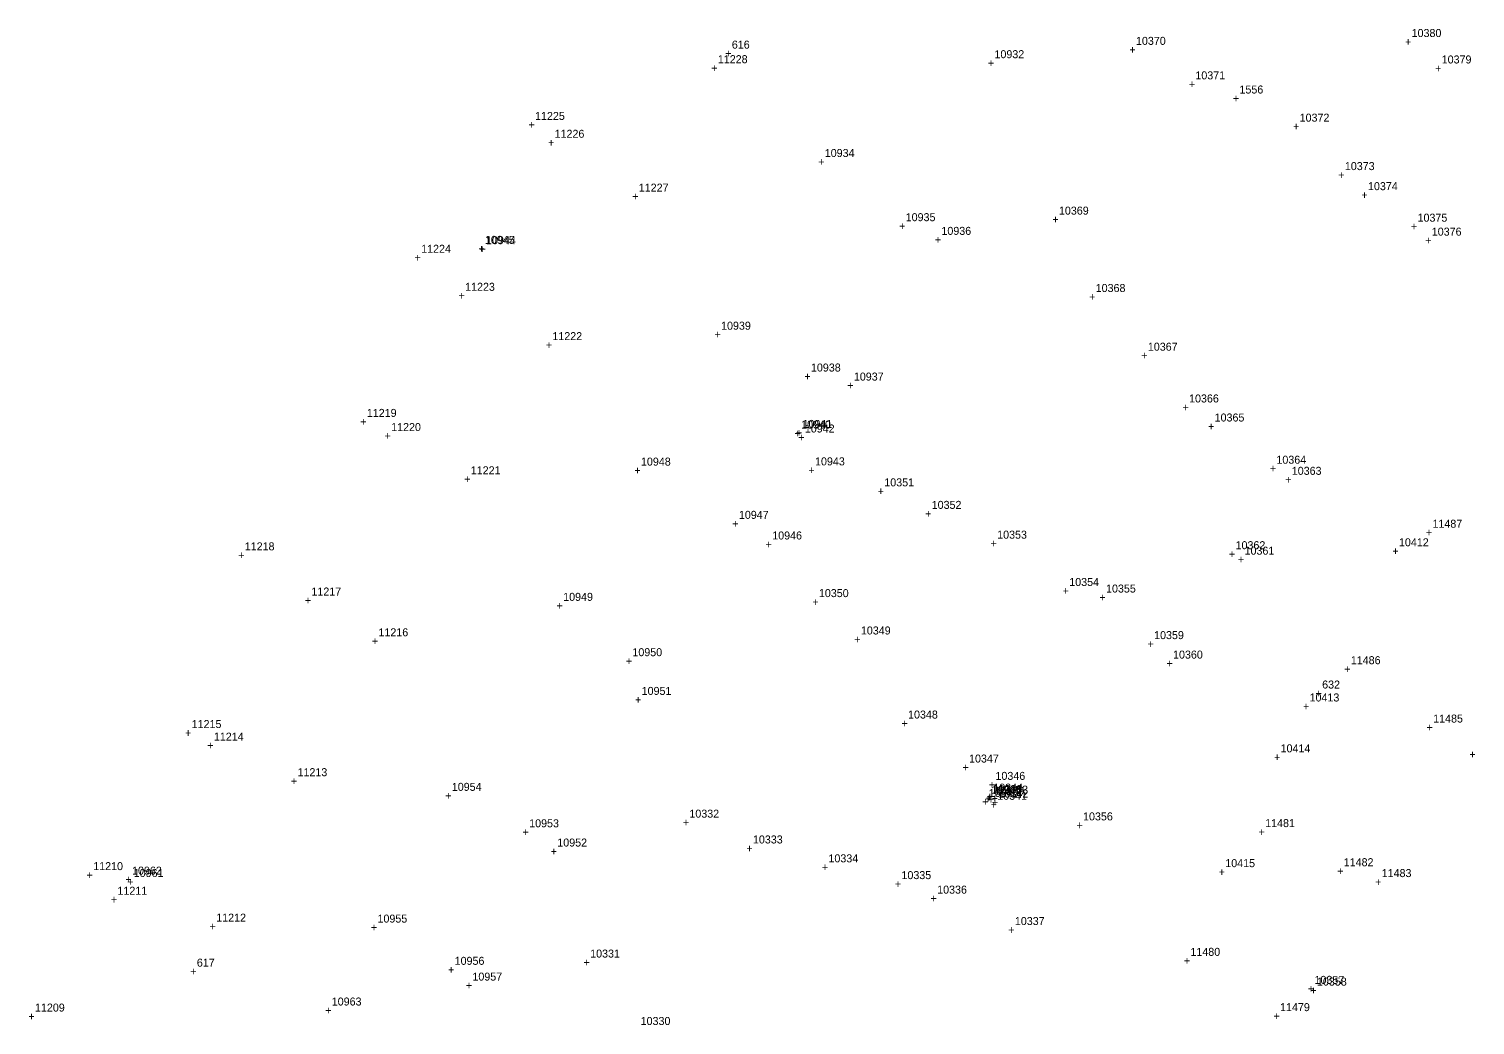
# Model space of a CAD drawing. Extents: x 1160051 to 1162814, y 614604 to 619560.
# Drawn here: x 1160823.2 to 1161275, y 616775.5 to 617086.8 of the extents above; entities that cross this region are included whole.
import ezdxf

# ---------------------------------------------------------------- set-up
doc = ezdxf.new("R2010")
doc.units = 0
for name, color, linetype in [('S_Control_Temp_Traverse', 7, 'Continuous'), ('S_Drainage_Culvert_Top', 7, 'Continuous'), ('S_Drainage_Invert', 7, 'Continuous'), ('S_Ground_Elevation', 7, 'Continuous'), ('S_Guardrail_Beam', 7, 'Continuous'), ('S_Utilities_UG_BoringLocation', 7, 'Continuous')]:
    doc.layers.add(name, color=color, linetype=linetype)

msp = doc.modelspace()

# ---------------------------------------------------------------- texts
at = {"layer": 'S_Control_Temp_Traverse'}
for s, p in [('616', (1161042.8, 617080.64)), ('+', (1161040.74, 617077.89)), ('632', (1161227.2, 616880.64)), ('+', (1161225.14, 616877.89)), ('617', (1160875.69, 616793.72)), ('+', (1160873.63, 616790.97))]:
    msp.add_text(s, height=2.5, dxfattribs=at).set_placement(p)
at = {"layer": 'S_Drainage_Culvert_Top'}
for s, p in [('10944', (1160966.03, 617019.51)), ('+', (1160963.97, 617016.76)), ('10941', (1161064.89, 616962.09)), ('+', (1161062.83, 616959.34)), ('10339', (1161124.84, 616847.45)), ('+', (1161122.78, 616844.7)), ('10961', (1160855.97, 616821.74)), ('+', (1160853.91, 616818.99)), ('+', (1161222.75, 616785.59)), ('10357', (1161224.81, 616788.34))]:
    msp.add_text(s, height=2.5, dxfattribs=at).set_placement(p)
at = {"layer": 'S_Drainage_Invert'}
for s, p in [('10945', (1160965.69, 617019.63)), ('+', (1160963.63, 617016.88)), ('10940', (1161064.45, 616961.89)), ('+', (1161062.39, 616959.14)), ('10338', (1161124.22, 616847.95)), ('+', (1161122.16, 616845.2)), ('10962', (1160855.45, 616822.48)), ('+', (1160853.38, 616819.73)), ('+', (1161223.53, 616785.05)), ('10358', (1161225.59, 616787.8))]:
    msp.add_text(s, height=2.5, dxfattribs=at).set_placement(p)
at = {"layer": 'S_Ground_Elevation'}
for s, p in [('10380', (1161255.15, 617084.27)), ('10932', (1161124.84, 617077.65)), ('+', (1161166.98, 617079.07)), ('10370', (1161169.04, 617081.82)), ('+', (1161253.09, 617081.52)), ('11228', (1161038.43, 617076.09)), ('+', (1161122.78, 617074.9)), ('10379', (1161264.54, 617076.01)), ('+', (1161036.36, 617073.34)), ('10371', (1161187.6, 617071.04)), ('+', (1161262.48, 617073.26)), ('+', (1161185.54, 617068.29)), ('+', (1160979.27, 617055.6)), ('11225', (1160981.33, 617058.35)), ('10372', (1161220.17, 617057.82)), ('11226', (1160987.44, 617052.78)), ('+', (1161218.11, 617055.07)), ('+', (1160985.38, 617050.03)), ('10934', (1161071.83, 617046.77)), ('+', (1161069.77, 617044.02)), ('10373', (1161234.29, 617042.68)), ('+', (1161232.23, 617039.93)), ('+', (1161011.67, 617033.2)), ('11227', (1161013.73, 617035.95)), ('+', (1161239.46, 617033.66)), ('10374', (1161241.52, 617036.41)), ('10369', (1161144.98, 617028.76)), ('+', (1161095.05, 617023.96)), ('10935', (1161097.11, 617026.71)), ('+', (1161142.92, 617026.01)), ('+', (1161254.94, 617023.8)), ('10375', (1161257, 617026.55)), ('+', (1161106.2, 617019.68)), ('10936', (1161108.27, 617022.43)), ('11224', (1160945.76, 617016.83)), ('+', (1160943.7, 617014.08)), ('+', (1160957.43, 617002.2)), ('11223', (1160959.49, 617004.95)), ('+', (1161154.4, 617001.83)), ('10368', (1161156.46, 617004.58)), ('10939', (1161039.44, 616992.79)), ('11222', (1160986.75, 616989.53)), ('+', (1161037.38, 616990.04)), ('+', (1160984.69, 616986.78)), ('+', (1161170.69, 616983.48)), ('10367', (1161172.75, 616986.23)), ('10938', (1161067.51, 616979.72)), ('+', (1161065.45, 616976.97)), ('+', (1161078.86, 616974.14)), ('10937', (1161080.92, 616976.89)), ('10366', (1161185.63, 616970.05)), ('11219', (1160928.79, 616965.54)), ('+', (1161183.57, 616967.3)), ('+', (1160926.73, 616962.79)), ('11220', (1160936.39, 616961.12)), ('10942', (1161065.61, 616960.66)), ('+', (1161191.55, 616961.35)), ('10365', (1161193.61, 616964.1)), ('+', (1160934.33, 616958.37)), ('+', (1161063.55, 616957.91)), ('11221', (1160961.25, 616947.6)), ('+', (1161012.36, 616947.57)), ('10948', (1161014.42, 616950.32)), ('+', (1161066.73, 616947.64)), ('10943', (1161068.79, 616950.39)), ('+', (1161210.85, 616948.16)), ('10364', (1161212.91, 616950.91)), ('+', (1160959.19, 616944.85)), ('10351', (1161090.43, 616943.83)), ('+', (1161088.37, 616941.08)), ('10947', (1161045.01, 616933.68)), ('+', (1161103.17, 616934.04)), ('10352', (1161105.23, 616936.79)), ('+', (1161042.95, 616930.93)), ('11487', (1161261.66, 616930.91)), ('+', (1161053.36, 616924.48)), ('10946', (1161055.42, 616927.23)), ('+', (1161123.62, 616924.73)), ('10353', (1161125.68, 616927.48)), ('10362', (1161200.15, 616924.19)), ('+', (1161259.6, 616928.16)), ('+', (1160888.59, 616921.08)), ('11218', (1160890.65, 616923.83)), ('+', (1161198.08, 616921.44)), ('10354', (1161148.2, 616912.69)), ('10355', (1161159.69, 616910.64)), ('+', (1160909.42, 616906.96)), ('11217', (1160911.48, 616909.71)), ('10949', (1160990.12, 616908.05)), ('+', (1161067.94, 616906.47)), ('10350', (1161070, 616909.22)), ('+', (1161146.14, 616909.94)), ('+', (1161157.63, 616907.89)), ('+', (1160988.06, 616905.3)), ('11216', (1160932.42, 616896.97)), ('10349', (1161083.11, 616897.54)), ('+', (1160930.36, 616894.22)), ('+', (1161081.05, 616894.79)), ('+', (1161172.65, 616893.34)), ('10359', (1161174.71, 616896.09)), ('10950', (1161011.74, 616890.75)), ('11486', (1161236.15, 616888.25)), ('+', (1161009.68, 616888)), ('+', (1161234.09, 616885.5)), ('+', (1161012.57, 616875.9)), ('10951', (1161014.63, 616878.65)), ('10348', (1161097.85, 616871.26)), ('11485', (1161261.88, 616870.01)), ('11215', (1160874.07, 616868.29)), ('+', (1161095.79, 616868.51)), ('+', (1161259.82, 616867.26)), ('+', (1160872.01, 616865.54)), ('+', (1160878.95, 616861.61)), ('11214', (1160881.01, 616864.36)), ('10347', (1161116.9, 616857.51)), ('+', (1161273.18, 616858.83)), ('11213', (1160907.14, 616853.25)), ('+', (1161114.84, 616854.76)), ('10346', (1161125.15, 616852.09)), ('+', (1160905.08, 616850.5)), ('10954', (1160955.33, 616848.67)), ('+', (1161123.09, 616849.34)), ('10345', (1161123.87, 616847.66)), ('10344', (1161124.47, 616848.43)), ('10343', (1161126.03, 616847.8)), ('+', (1160953.27, 616845.92)), ('+', (1161121.01, 616844.01)), ('+', (1161121.81, 616844.91)), ('+', (1161122.41, 616845.68)), ('10340', (1161123.07, 616846.76)), ('+', (1161123.65, 616843.12)), ('+', (1161123.97, 616845.05)), ('+', (1161124.06, 616843.79)), ('10341', (1161125.71, 616845.87)), ('10342', (1161126.12, 616846.54)), ('10332', (1161029.54, 616840.29)), ('10356', (1161152.51, 616839.43)), ('+', (1160977.44, 616834.53)), ('10953', (1160979.5, 616837.28)), ('+', (1161027.48, 616837.54)), ('+', (1161150.45, 616836.68)), ('+', (1161207.34, 616834.58)), ('11481', (1161209.4, 616837.33)), ('10952', (1160988.28, 616831.26)), ('10333', (1161049.39, 616832.22)), ('+', (1160986.22, 616828.51)), ('+', (1161047.33, 616829.47)), ('10334', (1161072.98, 616826.32)), ('11482', (1161233.94, 616825.11)), ('+', (1160841.25, 616821.13)), ('11210', (1160843.32, 616823.88)), ('+', (1161070.91, 616823.57)), ('10335', (1161095.79, 616821.08)), ('+', (1161231.88, 616822.36)), ('11483', (1161245.8, 616821.71)), ('11211', (1160850.89, 616816.2)), ('+', (1161093.73, 616818.33)), ('10336', (1161106.94, 616816.54)), ('+', (1161243.74, 616818.96)), ('+', (1160848.83, 616813.45)), ('+', (1161104.88, 616813.79)), ('11212', (1160881.74, 616807.78)), ('10955', (1160932.12, 616807.49)), ('10337', (1161131.21, 616806.72)), ('+', (1160879.68, 616805.03)), ('+', (1160930.06, 616804.74)), ('+', (1161129.15, 616803.97)), ('10956', (1160956.22, 616794.29)), ('+', (1160996.49, 616793.81)), ('10331', (1160998.55, 616796.56)), ('+', (1161183.99, 616794.35)), ('11480', (1161186.05, 616797.1)), ('+', (1160954.16, 616791.54)), ('10957', (1160961.77, 616789.36)), ('+', (1160959.71, 616786.61)), ('11209', (1160825.13, 616779.68)), ('10963', (1160917.83, 616781.57)), ('11479', (1161214.05, 616779.81)), ('+', (1160823.07, 616776.93)), ('+', (1160915.77, 616778.82)), ('10330', (1161014.32, 616775.49)), ('+', (1161211.99, 616777.06))]:
    msp.add_text(s, height=2.5, dxfattribs=at).set_placement(p)
at = {"layer": 'S_Guardrail_Beam'}
for s, p in [('+', (1161259.38, 617019.44)), ('10376', (1161261.44, 617022.19)), ('10363', (1161217.71, 616947.44)), ('+', (1161215.65, 616944.69)), ('10412', (1161251.19, 616925.1)), ('10361', (1161202.96, 616922.48)), ('+', (1161249.12, 616922.35)), ('+', (1161200.9, 616919.73)), ('10360', (1161180.62, 616890)), ('+', (1161178.56, 616887.25)), ('10413', (1161223.27, 616876.6)), ('+', (1161221.21, 616873.85)), ('10414', (1161214.22, 616860.7)), ('+', (1161212.16, 616857.95)), ('10415', (1161196.94, 616824.82)), ('+', (1161194.88, 616822.07))]:
    msp.add_text(s, height=2.5, dxfattribs=at).set_placement(p)
at = {"layer": 'S_Utilities_UG_BoringLocation'}
for s, p in [('1556', (1161201.37, 617066.61)), ('+', (1161199.31, 617063.86))]:
    msp.add_text(s, height=2.5, dxfattribs=at).set_placement(p)

doc.saveas('drawing.dxf')
